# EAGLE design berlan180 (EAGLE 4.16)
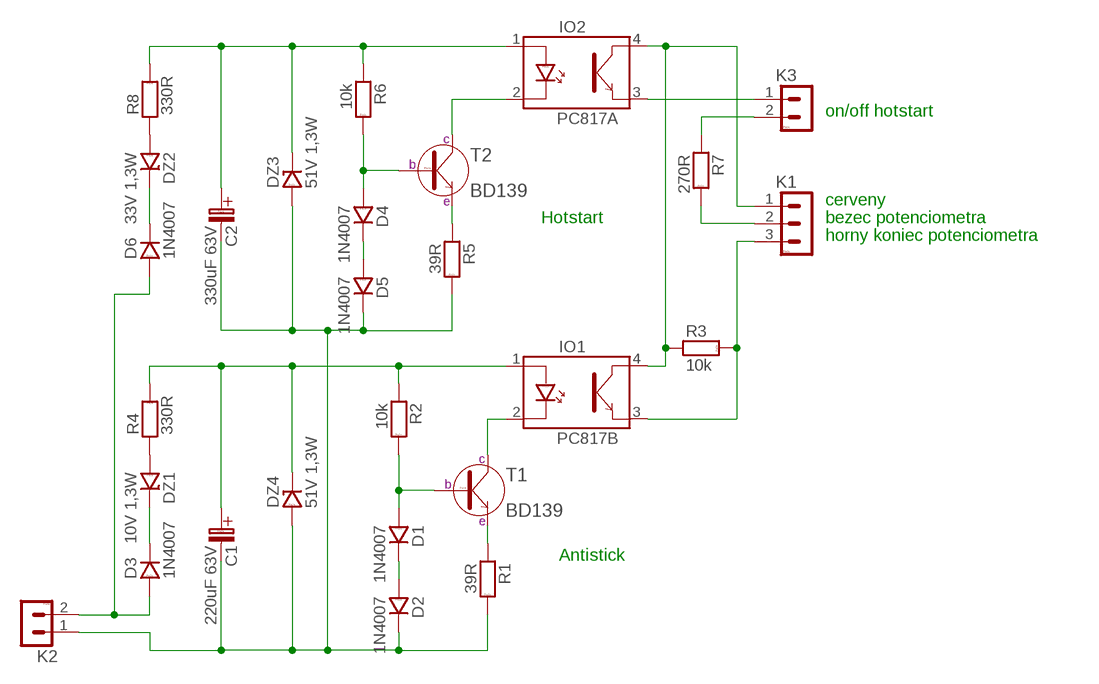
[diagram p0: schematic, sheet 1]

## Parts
C1  220uF 63V  C-ELEKTROLYT_5  [C-EL_5]
C2  330uF 63V  C-ELEKTROLYT_5  [C-EL_5]
D1  1N4007  1N4007_10  [D-10]
D2  1N4007  1N4007_10  [D-10]
D3  1N4007  1N4007_10  [D-10]
D4  1N4007  1N4007_10  [D-10]
D5  1N4007  1N4007_10  [D-10]
D6  1N4007  1N4007_10  [D-10]
DZ1  10V 1,3W  D-ZENEROVA_1,3W_BZX85V  [D-7,5]
DZ2  33V 1,3W  D-ZENEROVA_1,3W_BZX85V  [D-7,5]
DZ3  51V 1,3W  D-ZENEROVA_1,3W_BZX85V  [D-7,5]
DZ4  51V 1,3W  D-ZENEROVA_1,3W_BZX85V  [D-7,5]
IO1  PC817B  PC817  [DIL4]
IO2  PC817A  PC817  [DIL4]
K1  PSH02-03P  [PSH02-03P]
K2  PSH02-02P  [PSH02-02P]
K3  PSH02-02P  [PSH02-02P]
R1  39R  R_7,5  [R-7,5]
R2  10k  R_7,5  [R-7,5]
R3  10k  R_7,5  [R-7,5]
R4  330R  R_7,5  [R-7,5]
R5  39R  R_7,5  [R-7,5]
R6  10k  R_7,5  [R-7,5]
R7  270R  R_7,5  [R-7,5]
R8  330R  R_7,5  [R-7,5]
T1  BD139  [TO-126S]
T2  BD139  [TO-126S]

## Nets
N$1: C1.C+(C_EL+) DZ4.K IO1.1(A) R2.1 R4.2
N$2: IO1.2(K) T1.2(C)
N$3: D1.A R2.2 T1.3(B)
N$4: D1.K D2.A
N$5: C1.C-(C_EL-) C2.C-(C_EL-) D2.K D5.K DZ3.A DZ4.A K2.1 R1.2 R5.2
N$6: R1.1 T1.1(E)
N$7: IO1.3(E) K1.3 R3.2
N$8: IO1.4(C) IO2.4(C) K1.1 R3.1
N$9: DZ1.A R4.1
N$10: C2.C+(C_EL+) DZ3.K IO2.1(A) R6.1 R8.2
N$11: D3.A D6.A K2.2
N$12: D3.K DZ1.K
N$13: IO2.2(K) T2.2(C)
N$14: D4.A R6.2 T2.3(B)
N$15: D4.K D5.A
N$16: K1.2 R7.2
N$17: R5.1 T2.1(E)
N$18: IO2.3(E) K3.1
N$19: K3.2 R7.1
N$20: DZ2.A R8.1
N$22: D6.K DZ2.K

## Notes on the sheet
- on/off hotstart
- cerveny
- Hotstart | bezec potenciometra
- horny koniec potenciometra
- Antistick

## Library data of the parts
C1 C2 = #moje:C-ELEKTROLYT: Kondenzator - elektrolyticky
D1-D6 = #moje:1N4007: Usmernovaci dioda - 1A, 1000V
DZ1-DZ4 = #moje:D-ZENEROVA: Zenerova dioda
IO1 IO2 = #moje:PC817: Optoclen
K1 = #moje:PSH02-03: Konektory se zamkem - vidlice - 3pin
K2 K3 = #moje:PSH02-02: Konektory se zamkem - vidlice - 2pin
R1-R8 = #moje:R: Rezistor
T1 T2 = #moje:BD139: Tranzistor NPN - Vykonovy - Ic=1,5A

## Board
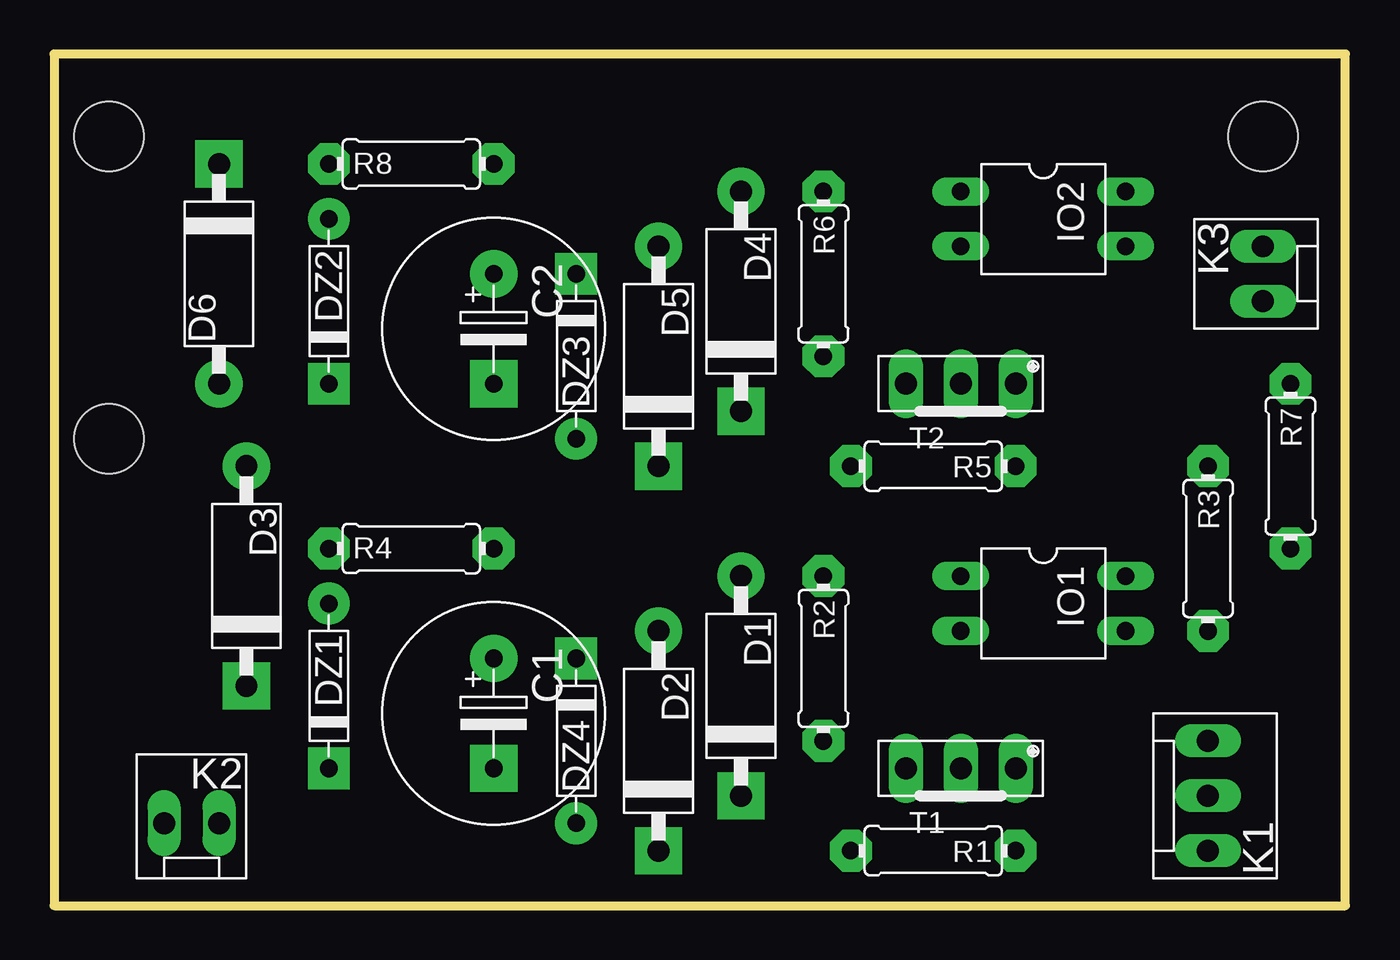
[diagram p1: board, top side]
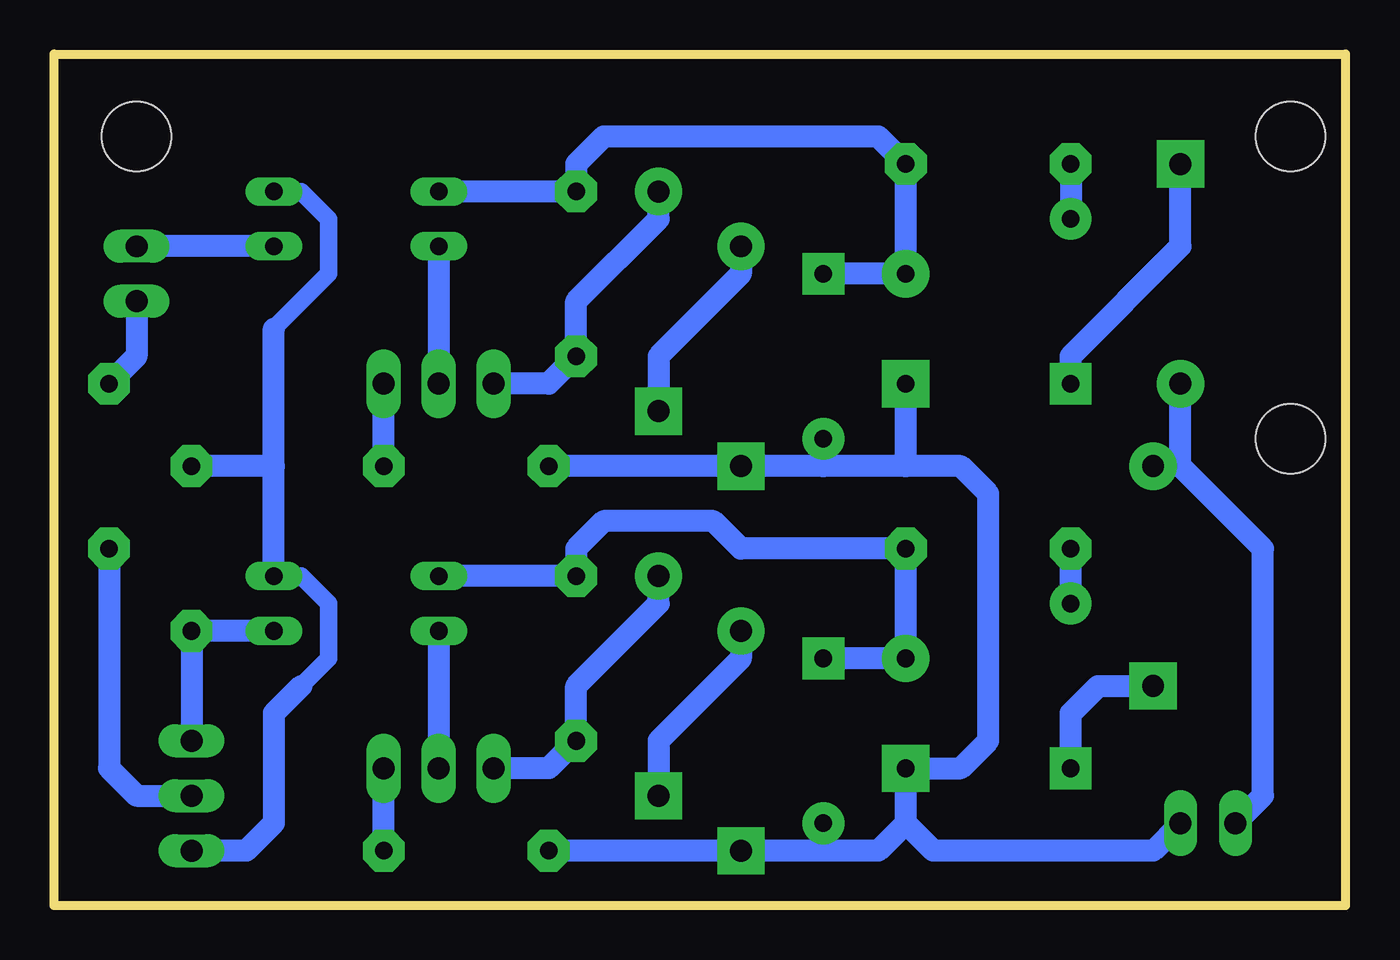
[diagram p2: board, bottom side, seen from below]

Size 59.69 x 39.37 mm. Coordinates in mm from the lower left corner, seen from the top.
Outline: 0,0 59.69,0 59.69,39.37 0,39.37 0,0
Copper layers (1*16): Top 0.035mm / dielectric 1.5mm / Bottom 0.035mm
Design rules "default": minimum track width 10mil, minimum drill 24mil, track to track 8mil, track to pad 8mil, pad to pad 8mil, via to via 8mil, smd to smd 8mil, copper to edge 40mil, drill to drill 8mil, minimum pad ring 10mil, minimum via ring 8mil, stop-mask expansion 4mil, vias tented up to drill 0mil, thermal gap 10mil
Holes 3.2 mm at 2.54,21.59 55.88,35.56 2.54,35.56
Holes 0.6 mm at 29.21,62.23

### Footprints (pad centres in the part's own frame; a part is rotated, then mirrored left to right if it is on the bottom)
C-EL_5 = drill 0.813 pad 2.184 round: C+ -2.54,0 | drill 0.813 pad 2.184 square: C- 2.54,0
D-10 = drill 1.016 pad 2.184 round: A -5.08,0 | drill 1.016 pad 2.184 square: K 5.08,0
D-7,5 = drill 0.813 pad 1.93 round: A -3.81,0 | drill 0.813 pad 1.93 square: K 3.81,0
DIL4 = drill 0.813 pad 1.27 long: 1 -1.27,-3.81; 2 1.27,-3.81; 3 1.27,3.81; 4 -1.27,3.81
PSH02-03P = drill 1.016 pad 1.422 long: 1 -2.54,0; 2 0,0; 3 2.54,0
PSH02-02P = drill 1.016 pad 1.422 long: 1 -1.27,0; 2 1.27,0
R-7,5 = drill 0.813 pad 1.93 octagon: 1 -3.81,0; 2 3.81,0
TO-126S = drill 1.016 pad 1.6 long: 1 -2.54,0; 2 0,0; 3 2.54,0

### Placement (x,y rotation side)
C1  20.32,8.89 270 top
C2  20.32,26.67 270 top
D1  31.75,10.16 270 top
D2  27.94,7.62 270 top
D3  8.89,15.24 270 top
D4  31.75,27.94 270 top
D5  27.94,25.4 270 top
D6  7.62,29.21 90 top
DZ1  12.7,10.16 270 top
DZ2  12.7,27.94 270 top
DZ3  24.13,25.4 90 top
DZ4  24.13,7.62 90 top
IO1  45.72,13.97 270 top
IO2  45.72,31.75 270 top
K1  53.34,5.08 90 top
K2  6.35,3.81 180 top
K3  55.88,29.21 270 top
R1  40.64,2.54 180 top
R2  35.56,11.43 270 top
R3  53.34,16.51 270 top
R4  16.51,16.51 0 top
R5  40.64,20.32 180 top
R6  35.56,29.21 270 top
R7  57.15,20.32 270 top
R8  16.51,34.29 0 top
T1  41.91,6.35 180 top
T2  41.91,24.13 180 top

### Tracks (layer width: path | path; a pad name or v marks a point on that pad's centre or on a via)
N$1
  Bottom 1.016: IO1.1 R2.1 35.56,16.51 34.29,17.78 29.21,17.78 27.94,16.51 R4.2 C1.C+ DZ4.K
N$2
  Bottom 1.016: IO1.2 T1.2
N$3
  Bottom 1.016: D1.A 31.75,13.97 35.56,10.16 R2.2 36.83,6.35 T1.3
N$4
  Bottom 1.016: D2.A 27.94,11.43 31.75,7.62 D1.K
N$5
  Bottom 1.016: R1.2 D2.K 24.13,2.54 | R5.2 D5.K 24.13,20.32 | 20.32,20.32 24.13,20.32 | 20.32,20.32 C2.C- | 24.13,2.54 21.59,2.54 20.32,3.81 | 20.32,3.81 C1.C- 17.78,6.35 16.51,7.62 16.51,19.05 17.78,20.32 20.32,20.32 | 20.32,3.81 19.05,2.54 8.89,2.54 K2.1 | 24.13,2.54 DZ4.A | 24.13,20.32 DZ3.A
N$6
  Bottom 1.016: R1.1 T1.1
N$7
  Bottom 1.016: IO1.3 R3.2 K1.3
N$8
  Bottom 0.813: IO2.4 48.26,33.02 46.99,31.75 46.99,29.21 49.53,26.67 | IO1.4 48.26,15.24 46.99,13.97 46.99,11.43 48.26,10.16
  Bottom 1.016: IO1.4 49.53,20.32 | 49.53,20.32 49.53,26.67 | 49.53,20.32 R3.1 | 48.26,10.16 49.53,8.89 49.53,3.81 50.8,2.54 K1.1
N$9
  Bottom 1.016: DZ1.A R4.1
N$10
  Bottom 1.016: IO2.1 R6.1 35.56,34.29 34.29,35.56 21.59,35.56 R8.2 C2.C+ DZ3.K
N$11
  Bottom 1.016: K2.2 3.81,5.08 3.81,16.51 7.62,20.32 | 7.62,20.32 D3.A | 7.62,20.32 D6.A
N$12
  Bottom 1.016: DZ1.K 12.7,8.89 11.43,10.16 D3.K
N$13
  Bottom 1.016: IO2.2 T2.2
N$14
  Bottom 1.016: D4.A 31.75,31.75 35.56,27.94 R6.2 36.83,24.13 T2.3
N$15
  Bottom 1.016: D5.A 27.94,29.21 31.75,25.4 D4.K
N$16
  Bottom 1.016: R7.2 57.15,6.35 55.88,5.08 K1.2
N$17
  Bottom 1.016: R5.1 T2.1
N$18
  Bottom 1.016: IO2.3 K3.1
N$19
  Bottom 1.016: K3.2 55.88,25.4 R7.1
N$20
  Bottom 1.016: R8.1 DZ2.A
N$22
  Bottom 1.016: DZ2.K 12.7,25.4 7.62,30.48 D6.K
